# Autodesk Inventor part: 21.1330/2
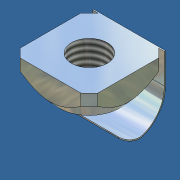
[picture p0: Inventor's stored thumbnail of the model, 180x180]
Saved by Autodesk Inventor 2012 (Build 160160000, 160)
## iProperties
Created: 2006-12
Part Number: 21.1330/2
Document SubType Name: Modeling
Designer: Andy Moles
Material: Steel, Mild
Density: 7.86 g/cm^3
Description: M6 SQUARE NUT POS FXG
Mass: 5.20492 g
Surface Area: 8.43697 cm^2
Volume: 0.662203 cm^3
Vendor: S
Title: M6 SQUARE NUT POS FXG
Author: Andy Moles
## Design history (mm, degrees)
sketch "Sketch2"
  geometry: L1 (-5.086, -6.5)-(5.086, -6.5); L2 (6.5, -5.086)-(6.5, 5.086); L3 (5.086, 6.5)-(-5.086, 6.5); L4 (-6.5, 5.086)-(-6.5, -5.086); L5 (-6.5, 6.5)-(6.5, -6.5); L6 (5.086, 6.5)-(6.5, 5.086); L7 (0, -6.5)-(0, 6.5); L8 (-6.5, 0)-(6.5, 0); L9 (-5.086, 6.5)-(-6.5, 5.086); L10 (-5.086, -6.5)-(-6.5, -5.086); L11 (5.086, -6.5)-(6.5, -5.086); C1 r 3 at (0, 0); 2 further points
  constraints: 22 end point, 6 symmetric about line, 4 parallel, 3 midpoint, 2 coincident, 2 perpendicular, 1 centre point, 1 horizontal
  dimensions: "THREAD" = 6 diameter of C1; "d3" = 45 deg angle of L3 L6 (derived); "d4" = 2 distance of L3.start L2.end
extrude "Extrusion1" new body sketch "Sketch2" distance "d5" = 5.5; taper "d6" = 0 deg
workplane "Work Plane1"
sketch "Sketch4"
  geometry: L1 (11.192, 0)-(5.192, 0) reference; L2 (8.192, 0)-(13.192, 0); L3 (16.385, 5.5)-(16.385, 3.5); L4 (13.192, 0)-(16.797, 3.952); L5 (13.192, 0)-(16.385, 0); L6 (16.385, 3.5)-(16.385, 0); L7 (16.797, 3.952)-(16.797, -0.412); L8 (16.797, -0.412)-(13.192, -0.412); L9 (13.192, -0.412)-(13.192, 0); L10 (8.192, 5.5)-(8.192, 0); L11 (16.385, 5.5)-(16.385, 0) reference; L12 (16.385, 3.5)-(17.502, 3.5); L13 (9.192, 5.5)-(16.385, 5.5) reference
  constraints: 20 end point, 6 perpendicular, 1 collinear, 1 midpoint, 1 parallel, 1 point on line
  dimensions: "d10" = 5 distance of L2.start L2.end; "d15" = 2 distance between parallel lines of L12 L13
revolve "Revolution1" sketch "Sketch4" stored, may be unused: angle "d12" = 90 deg
thread "Thread1" dims "d13" = 10, "d14" = 0
sketch "Sketch6"
  geometry: L1 (2.954, -2.535)-(2.954, 6.006); L2 (2.954, -2.535)-(2.954, -7.535); L3 (2.954, -2.535)-(3.154, -2.535); L4 (3.154, -2.535)-(3.154, -7.535); L5 (-2.646, -13.135)-(-2.646, -13.335); L6 (2.954, 0)-(2.954, -1.933); L7 (-8.632, -2.535)-(1.539, -2.535) reference; L8 (2.954, -2.535)-(2.954, -4.468) reference; A1 r 5.374 centre (-2.416, -7.766) between (-2.646, -13.135) and (2.954, -7.535); A2 r 5.574 centre (-2.416, -7.766) between (-2.646, -13.335) and (3.154, -7.535); 4 further points; 1 other entity
  constraints: 12 end point, 4 collinear, 4 point on circle, 2 centre point, 2 parallel, 2 perpendicular, 1 coincident, 1 horizontal, 3 other
  dimensions: "d25" = 5 distance of L1.start L2.end; "d23" = 0.2 distance of L1.start L3.end; "d22" = 0.2 distance of L5.start L5.end; "d21" = 10.8 distance from line of L5.end L3; "d24" = 5.37434 radius of A1
extrude "Extrusion3" join sketch "Sketch6" taper "d27" = 0 deg; stored distance "d28" = 12
fillet "Fillet2" dims "d29" = 2
body "Solid1"
